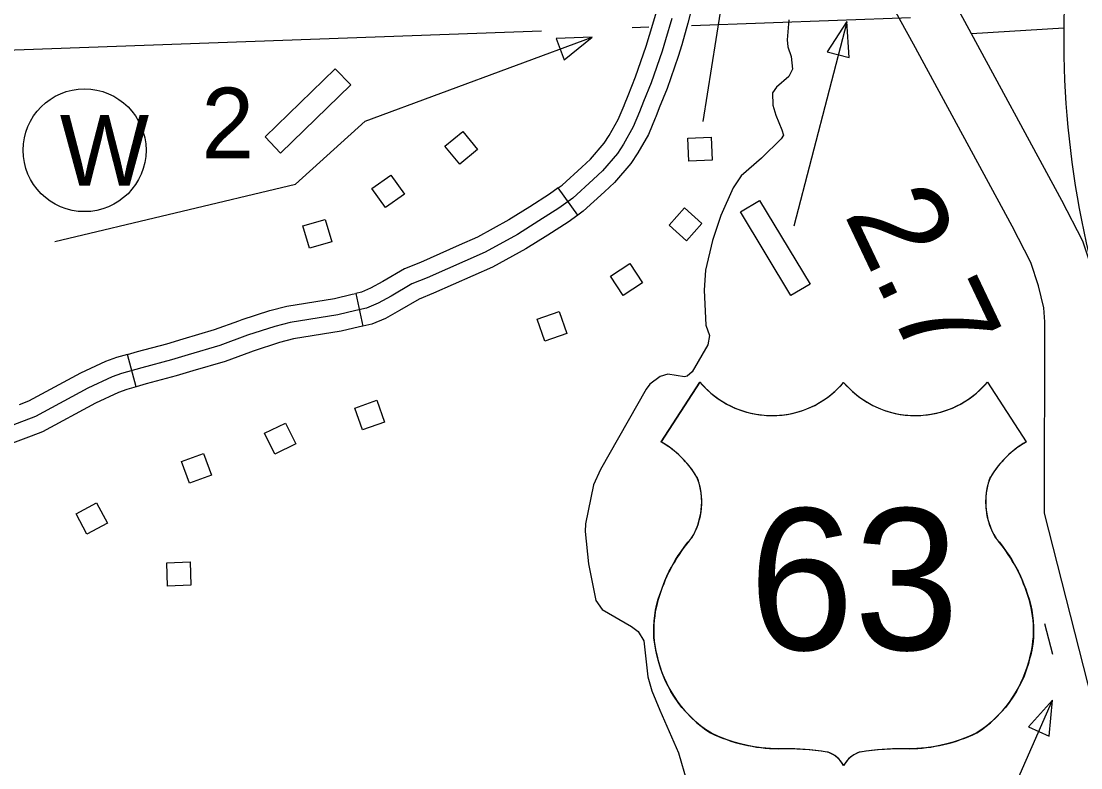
# Model space of a CAD drawing. Extents: x 1671357 to 13005564, y 567358 to 14261451.
# Drawn here: x 12758298.676 to 12758300.259, y 14259942.041 to 14259943.158 of the extents above; entities that cross this region are included whole.
import ezdxf

# ---------------------------------------------------------------- set-up
doc = ezdxf.new("R2010")
doc.units = 0
for name, color, linetype in [('15', 7, 'Continuous'), ('22', 7, 'Continuous'), ('31', 7, 'Continuous'), ('32', 7, 'Continuous'), ('35', 7, 'Continuous'), ('4', 7, 'Continuous'), ('48', 7, 'Continuous'), ('49', 7, 'Continuous'), ('56', 7, 'Continuous'), ('57', 7, 'Continuous'), ('63', 7, 'Continuous')]:
    doc.layers.add(name, color=color, linetype=linetype)

msp = doc.modelspace()

# ---------------------------------------------------------------- linework, layer by layer
at = {"layer": '15'}
for points in [[(12758299.593, 14259943.9275), (12758299.6236, 14259943.8747), (12758299.6719, 14259943.806), (12758299.8204, 14259943.6294), (12758299.8655, 14259943.5569), (12758300.0827, 14259943.1633), (12758300.2306, 14259942.8901), (12758300.2619, 14259942.8294), (12758300.2768, 14259942.7845), (12758300.2866, 14259942.742), (12758300.2893, 14259942.7116), (12758300.2887, 14259942.4326), (12758300.6474, 14259941.0247)], [(12758300.5675, 14259941.0004), (12758300.2052, 14259942.4222), (12758300.2058, 14259942.7081), (12758300.204, 14259942.7289), (12758300.1964, 14259942.7619), (12758300.1847, 14259942.7969), (12758300.1568, 14259942.8511), (12758300.0094, 14259943.1233), (12758299.7935, 14259943.5146), (12758299.7527, 14259943.5802), (12758299.6057, 14259943.7551), (12758299.5532, 14259943.8296), (12758299.5425, 14259943.8482), (12758299.5157, 14259943.9046)]]:
    msp.add_lwpolyline(points, dxfattribs=at)
at = {"layer": '22'}
for p, q in [((12758299.6902, 14259942.6181), (12758299.6324, 14259942.5287)), ((12758300.1199, 14259942.6181), (12758300.1776, 14259942.5287))]:
    msp.add_line(p, q, dxfattribs=at)
for centre, radius, start, end in [((12758299.7978, 14259942.7086), 0.1406, 220.075, 319.6701), ((12758300.0122, 14259942.7086), 0.1406, 220.3299, 319.925), ((12758299.5569, 14259942.399), 0.1501, 30.7809, 59.9883), ((12758300.2532, 14259942.399), 0.1501, 120.0117, 149.2191), ((12758299.59, 14259942.4386), 0.1029, 328.8105, 21.2108), ((12758300.2201, 14259942.4386), 0.1029, 158.7892, 211.1895), ((12758299.8591, 14259942.2276), 0.2401, 138.9565, 162.6913), ((12758299.951, 14259942.2276), 0.2401, 17.3087, 41.0435), ((12758299.7798, 14259942.2473), 0.1586, 160.9576, 197.3819), ((12758300.0302, 14259942.2473), 0.1586, 342.6181, 19.0424), ((12758299.8056, 14259942.2478), 0.1836, 195.1074, 237.1312), ((12758300.0044, 14259942.2478), 0.1836, 302.8688, 344.8926), ((12758299.8091, 14259942.3056), 0.2357, 244.0771, 269.5779), ((12758300.001, 14259942.3056), 0.2357, 270.4221, 295.9229), ((12758299.8145, 14259941.6381), 0.4318, 81.1942, 90.9539), ((12758299.8685, 14259942.0253), 0.0414, 28.0342, 72.9864), ((12758299.9416, 14259942.0253), 0.0414, 107.0136, 151.9658), ((12758299.9955, 14259941.6381), 0.4318, 89.0461, 98.8058)]:
    msp.add_arc(centre, radius, start, end, dxfattribs=at)
at = {"layer": '31'}
for p, q in [((12758299.5076, 14259942.8677), (12758299.4783, 14259942.9083)), ((12758299.1761, 14259942.7507), (12758299.1863, 14259942.7017)), ((12758299.0012, 14259942.7099), (12758299.0012, 14259942.7099)), ((12758298.8479, 14259942.6111), (12758298.8346, 14259942.6594))]:
    msp.add_line(p, q, dxfattribs=at)
for points in [[(12758299.5776, 14259943.0332), (12758299.5829, 14259943.0467), (12758299.5942, 14259943.0745), (12758299.6101, 14259943.1203), (12758299.6149, 14259943.1366), (12758299.6241, 14259943.1681), (12758299.629, 14259943.1875), (12758299.6309, 14259943.1966)], [(12758299.6799, 14259943.1864), (12758299.6778, 14259943.1762), (12758299.6724, 14259943.1549), (12758299.663, 14259943.1226), (12758299.6579, 14259943.105), (12758299.6411, 14259943.0569), (12758299.6294, 14259943.0281), (12758299.6242, 14259943.0149)], [(12758299.6483, 14259943.1615), (12758299.639, 14259943.1296), (12758299.634, 14259943.1127), (12758299.6176, 14259943.0657), (12758299.6061, 14259943.0374), (12758299.6001, 14259943.0221), (12758299.5907, 14259942.9995), (12758299.5761, 14259942.9738), (12758299.567, 14259942.96), (12758299.5448, 14259942.9339), (12758299.5306, 14259942.9209), (12758299.5001, 14259942.8931), (12758299.4793, 14259942.8781), (12758299.4494, 14259942.8591), (12758299.4176, 14259942.839), (12758299.3693, 14259942.8125), (12758299.2824, 14259942.7739), (12758299.2598, 14259942.7649), (12758299.2288, 14259942.7468), (12758299.2092, 14259942.7359), (12758299.1922, 14259942.7285), (12758299.176, 14259942.7251), (12758299.1492, 14259942.7186), (12758299.0779, 14259942.7072), (12758299.0548, 14259942.7012), (12758299.0142, 14259942.688), (12758298.9728, 14259942.6729), (12758298.9253, 14259942.6588), (12758298.9006, 14259942.6514), (12758298.8563, 14259942.6394), (12758298.826, 14259942.6311), (12758298.8118, 14259942.6258), (12758298.7758, 14259942.6092), (12758298.6972, 14259942.5666)], [(12758299.4783, 14259942.9083), (12758299.4843, 14259942.9126), (12758299.5137, 14259942.9394), (12758299.5267, 14259942.9513), (12758299.547, 14259942.9751), (12758299.5548, 14259942.9869), (12758299.5682, 14259943.0106), (12758299.5769, 14259943.0315), (12758299.5776, 14259943.0332)], [(12758299.6242, 14259943.0149), (12758299.6233, 14259943.0127), (12758299.6133, 14259942.9885), (12758299.5975, 14259942.9607), (12758299.5871, 14259942.9449), (12758299.5628, 14259942.9165), (12758299.5475, 14259942.9024), (12758299.5159, 14259942.8736), (12758299.5076, 14259942.8677)], [(12758299.4783, 14259942.9083), (12758299.4653, 14259942.8989), (12758299.436, 14259942.8803), (12758299.4048, 14259942.8606), (12758299.3581, 14259942.8349), (12758299.3306, 14259942.8227)], [(12758299.5076, 14259942.8677), (12758299.4934, 14259942.8574), (12758299.4628, 14259942.838), (12758299.4303, 14259942.8174), (12758299.3804, 14259942.79), (12758299.3509, 14259942.7769)], [(12758299.3306, 14259942.8227), (12758299.2727, 14259942.797), (12758299.2488, 14259942.7875), (12758299.2164, 14259942.7686), (12758299.1981, 14259942.7584), (12758299.1845, 14259942.7525), (12758299.1761, 14259942.7507)], [(12758299.3509, 14259942.7769), (12758299.2921, 14259942.7508), (12758299.2708, 14259942.7423), (12758299.2412, 14259942.725), (12758299.2203, 14259942.7134), (12758299.1998, 14259942.7045), (12758299.1863, 14259942.7017)], [(12758299.0012, 14259942.7099), (12758299.0061, 14259942.7117), (12758299.0477, 14259942.7252), (12758299.0727, 14259942.7317), (12758299.1442, 14259942.7432), (12758299.1705, 14259942.7495), (12758299.1761, 14259942.7507)], [(12758298.8346, 14259942.6594), (12758298.8498, 14259942.6636), (12758298.8937, 14259942.6754), (12758298.9182, 14259942.6828), (12758298.9649, 14259942.6967), (12758299.0012, 14259942.7099)], [(12758299.1863, 14259942.7017), (12758299.1815, 14259942.7007), (12758299.1541, 14259942.694), (12758299.083, 14259942.6826), (12758299.0618, 14259942.6771), (12758299.0224, 14259942.6644), (12758299.0184, 14259942.6629)], [(12758298.8346, 14259942.6594), (12758298.8183, 14259942.6549), (12758298.8022, 14259942.6489), (12758298.7646, 14259942.6316), (12758298.6867, 14259942.5894), (12758298.6731, 14259942.5842)], [(12758299.0184, 14259942.6629), (12758298.9807, 14259942.6491), (12758298.9325, 14259942.6348), (12758298.9075, 14259942.6273), (12758298.8629, 14259942.6153), (12758298.8479, 14259942.6111)], [(12758298.8479, 14259942.6111), (12758298.8337, 14259942.6072), (12758298.8215, 14259942.6027), (12758298.787, 14259942.5868), (12758298.7076, 14259942.5438), (12758298.6908, 14259942.5374)], [(12758298.6972, 14259942.5666), (12758298.6146, 14259942.5352), (12758298.572, 14259942.5309), (12758298.5393, 14259942.5213), (12758298.5057, 14259942.5012), (12758298.4691, 14259942.4706), (12758298.4448, 14259942.4415), (12758298.4283, 14259942.4191), (12758298.397, 14259942.3984), (12758298.3062, 14259942.3534), (12758298.2767, 14259942.3653)], [(12758298.6908, 14259942.5374), (12758298.6204, 14259942.5107), (12758298.5768, 14259942.5062), (12758298.5494, 14259942.4981), (12758298.5287, 14259942.4858)]]:
    msp.add_lwpolyline(points, dxfattribs=at)
at = {"layer": '32'}
msp.add_lwpolyline([(12758300.234, 14259943.1472), (12758300.0958, 14259943.139)], dxfattribs=at)
at = {"layer": '35'}
for points in [[(12758299.8233, 14259943.1596), (12758299.8206, 14259943.13), (12758299.8214, 14259943.1196), (12758299.8264, 14259943.1048), (12758299.8285, 14259943.0861), (12758299.8233, 14259943.0751), (12758299.8049, 14259943.0593), (12758299.7986, 14259943.0506), (12758299.7994, 14259943.0319), (12758299.8037, 14259943.017), (12758299.8126, 14259942.9953), (12758299.815, 14259942.9873), (12758299.8116, 14259942.9818), (12758299.7824, 14259942.9527), (12758299.7521, 14259942.9263), (12758299.7399, 14259942.9087), (12758299.7216, 14259942.867), (12758299.7092, 14259942.83), (12758299.6987, 14259942.7856), (12758299.6966, 14259942.7557), (12758299.6992, 14259942.7032), (12758299.7045, 14259942.6877), (12758299.7018, 14259942.6738), (12758299.6788, 14259942.6333), (12758299.6714, 14259942.6269), (12758299.6674, 14259942.6258), (12758299.6422, 14259942.6297), (12758299.6307, 14259942.6265), (12758299.6154, 14259942.6152), (12758299.6101, 14259942.6076)], [(12758299.6101, 14259942.6076), (12758299.5419, 14259942.4872), (12758299.5311, 14259942.4644), (12758299.5192, 14259942.4063), (12758299.5187, 14259942.3945), (12758299.5238, 14259942.3465), (12758299.5346, 14259942.2916), (12758299.5441, 14259942.2782), (12758299.5882, 14259942.2525), (12758299.5981, 14259942.2452), (12758299.6064, 14259942.2311), (12758299.6124, 14259942.1774), (12758299.6186, 14259942.1562), (12758299.6303, 14259942.1275), (12758299.6581, 14259942.0639), (12758299.6708, 14259942.0208), (12758299.6747, 14259941.9965), (12758299.6858, 14259941.9685), (12758299.6935, 14259941.8967), (12758299.7025, 14259941.8542), (12758299.7029, 14259941.7993), (12758299.7096, 14259941.7633), (12758299.7181, 14259941.7338)]]:
    msp.add_lwpolyline(points, dxfattribs=at)
at = {"layer": '4'}
for points in [[(12758300.0049, 14259943.1627), (12758299.6776, 14259943.1509)], [(12758299.4537, 14259943.1428), (12758298.5281, 14259943.1095), (12758298.5162, 14259943.1071), (12758297.6615, 14259943.0625)], [(12758299.6139, 14259943.1486), (12758299.5888, 14259943.1477)]]:
    msp.add_lwpolyline(points, dxfattribs=at)
at = {"layer": '49'}
for points in [[(12758299.6913, 14259942.1041), (12758299.6843, 14259942.11), (12758299.6776, 14259942.1163), (12758299.6696, 14259942.1245), (12758299.6634, 14259942.1317), (12758299.6579, 14259942.1388), (12758299.6523, 14259942.1468), (12758299.6469, 14259942.1556), (12758299.6427, 14259942.1632), (12758299.6389, 14259942.171), (12758299.6356, 14259942.1786), (12758299.6318, 14259942.1889), (12758299.6291, 14259942.1974), (12758299.6271, 14259942.2042), (12758299.6256, 14259942.2102), (12758299.6241, 14259942.2171), (12758299.6226, 14259942.2262), (12758299.6216, 14259942.2358), (12758299.6212, 14259942.244), (12758299.6212, 14259942.2523), (12758299.6218, 14259942.2612), (12758299.6227, 14259942.2693), (12758299.624, 14259942.2771), (12758299.6259, 14259942.2859), (12758299.628, 14259942.2935), (12758299.6303, 14259942.3004), (12758299.6331, 14259942.3087), (12758299.6356, 14259942.3155), (12758299.6378, 14259942.3208), (12758299.6409, 14259942.328), (12758299.6444, 14259942.3352), (12758299.6477, 14259942.3415), (12758299.6506, 14259942.3467), (12758299.6539, 14259942.3523), (12758299.6578, 14259942.3586), (12758299.6621, 14259942.3649), (12758299.6667, 14259942.3713), (12758299.6724, 14259942.3786), (12758299.677, 14259942.3842), (12758299.6809, 14259942.3903), (12758299.6846, 14259942.3982), (12758299.687, 14259942.4043), (12758299.6887, 14259942.4098), (12758299.6903, 14259942.4159), (12758299.6915, 14259942.4217), (12758299.6923, 14259942.4278), (12758299.6927, 14259942.4327), (12758299.6929, 14259942.4389), (12758299.6926, 14259942.4455), (12758299.6919, 14259942.4524), (12758299.6907, 14259942.4598), (12758299.689, 14259942.4667), (12758299.6867, 14259942.4736), (12758299.6838, 14259942.4793), (12758299.6806, 14259942.4841), (12758299.6773, 14259942.4887), (12758299.674, 14259942.4929), (12758299.6707, 14259942.4969), (12758299.6662, 14259942.502), (12758299.6617, 14259942.5065), (12758299.6573, 14259942.5106), (12758299.6523, 14259942.5149), (12758299.6461, 14259942.5197), (12758299.6415, 14259942.523), (12758299.6365, 14259942.5263), (12758299.6324, 14259942.5287), (12758299.6902, 14259942.6181), (12758299.6937, 14259942.6141), (12758299.6979, 14259942.6096), (12758299.7023, 14259942.6054), (12758299.7065, 14259942.6017), (12758299.7116, 14259942.5975), (12758299.7174, 14259942.5932), (12758299.7238, 14259942.589), (12758299.7295, 14259942.5857), (12758299.7357, 14259942.5824), (12758299.7425, 14259942.5793), (12758299.7499, 14259942.5764), (12758299.7587, 14259942.5735), (12758299.7659, 14259942.5717), (12758299.7737, 14259942.5701), (12758299.7799, 14259942.5691), (12758299.786, 14259942.5685), (12758299.7925, 14259942.5681), (12758299.7998, 14259942.568), (12758299.8089, 14259942.5684), (12758299.8156, 14259942.5691), (12758299.8228, 14259942.5702), (12758299.8296, 14259942.5716), (12758299.837, 14259942.5736), (12758299.8452, 14259942.5762), (12758299.8523, 14259942.579), (12758299.8617, 14259942.5833), (12758299.869, 14259942.5874), (12758299.8755, 14259942.5914), (12758299.8815, 14259942.5956), (12758299.8865, 14259942.5995), (12758299.8917, 14259942.6039), (12758299.8964, 14259942.6084), (12758299.9006, 14259942.6127), (12758299.905, 14259942.6176)], [(12758299.905, 14259942.6176), (12758299.9094, 14259942.6127), (12758299.9136, 14259942.6084), (12758299.9184, 14259942.6039), (12758299.9235, 14259942.5995), (12758299.9285, 14259942.5956), (12758299.9345, 14259942.5914), (12758299.941, 14259942.5874), (12758299.9484, 14259942.5833), (12758299.9577, 14259942.579), (12758299.9649, 14259942.5762), (12758299.973, 14259942.5736), (12758299.9804, 14259942.5716), (12758299.9873, 14259942.5702), (12758299.9945, 14259942.5691), (12758300.0011, 14259942.5684), (12758300.0102, 14259942.568), (12758300.0176, 14259942.5681), (12758300.024, 14259942.5685), (12758300.0301, 14259942.5691), (12758300.0363, 14259942.5701), (12758300.0441, 14259942.5717), (12758300.0513, 14259942.5735), (12758300.0601, 14259942.5764), (12758300.0676, 14259942.5793), (12758300.0743, 14259942.5824), (12758300.0805, 14259942.5857), (12758300.0862, 14259942.589), (12758300.0926, 14259942.5932), (12758300.0985, 14259942.5975), (12758300.1035, 14259942.6017), (12758300.1078, 14259942.6054), (12758300.1121, 14259942.6096), (12758300.1164, 14259942.6141), (12758300.1199, 14259942.6181), (12758300.1776, 14259942.5287), (12758300.1735, 14259942.5263), (12758300.1686, 14259942.523), (12758300.1639, 14259942.5197), (12758300.1577, 14259942.5149), (12758300.1528, 14259942.5106), (12758300.1484, 14259942.5065), (12758300.1439, 14259942.502), (12758300.1393, 14259942.4969), (12758300.136, 14259942.4929), (12758300.1328, 14259942.4887), (12758300.1295, 14259942.4841), (12758300.1263, 14259942.4793), (12758300.1233, 14259942.4736), (12758300.1211, 14259942.4667), (12758300.1194, 14259942.4598), (12758300.1181, 14259942.4524), (12758300.1174, 14259942.4455), (12758300.1172, 14259942.4389), (12758300.1174, 14259942.4327), (12758300.1178, 14259942.4278), (12758300.1186, 14259942.4217), (12758300.1197, 14259942.4159), (12758300.1213, 14259942.4098), (12758300.1231, 14259942.4043), (12758300.1254, 14259942.3982), (12758300.1292, 14259942.3903), (12758300.1331, 14259942.3842), (12758300.1377, 14259942.3786), (12758300.1434, 14259942.3713), (12758300.148, 14259942.3649), (12758300.1522, 14259942.3586), (12758300.1562, 14259942.3523), (12758300.1595, 14259942.3467), (12758300.1624, 14259942.3415), (12758300.1656, 14259942.3352), (12758300.1691, 14259942.328), (12758300.1723, 14259942.3208), (12758300.1744, 14259942.3155), (12758300.177, 14259942.3087), (12758300.1798, 14259942.3004), (12758300.182, 14259942.2935), (12758300.1841, 14259942.2859), (12758300.1861, 14259942.2771), (12758300.1874, 14259942.2693), (12758300.1883, 14259942.2612), (12758300.1888, 14259942.2523), (12758300.1889, 14259942.244), (12758300.1885, 14259942.2358), (12758300.1875, 14259942.2262), (12758300.186, 14259942.2171), (12758300.1845, 14259942.2102), (12758300.1829, 14259942.2042), (12758300.181, 14259942.1974), (12758300.1783, 14259942.1889), (12758300.1745, 14259942.1786), (12758300.1712, 14259942.171), (12758300.1674, 14259942.1632), (12758300.1632, 14259942.1556), (12758300.1578, 14259942.1468), (12758300.1521, 14259942.1388), (12758300.1467, 14259942.1317), (12758300.1405, 14259942.1245), (12758300.1325, 14259942.1163), (12758300.1257, 14259942.11), (12758300.1188, 14259942.1041)], [(12758299.905, 14259942.0447), (12758299.9025, 14259942.0489), (12758299.8997, 14259942.0525), (12758299.8962, 14259942.056), (12758299.8926, 14259942.0589), (12758299.89, 14259942.0606), (12758299.887, 14259942.0623), (12758299.8817, 14259942.0645), (12758299.8774, 14259942.0653), (12758299.8721, 14259942.0661), (12758299.8633, 14259942.0671), (12758299.8544, 14259942.0681), (12758299.8473, 14259942.0687), (12758299.8402, 14259942.0692), (12758299.8321, 14259942.0696), (12758299.8235, 14259942.0698), (12758299.8149, 14259942.0699), (12758299.806, 14259942.0699), (12758299.7957, 14259942.0702), (12758299.7822, 14259942.0714), (12758299.7714, 14259942.0729), (12758299.7615, 14259942.0747), (12758299.7508, 14259942.0772), (12758299.7414, 14259942.0798), (12758299.731, 14259942.0832), (12758299.7182, 14259942.0881), (12758299.7073, 14259942.093), (12758299.6986, 14259942.0986), (12758299.6913, 14259942.1041)], [(12758300.1188, 14259942.1041), (12758300.1115, 14259942.0986), (12758300.1028, 14259942.093), (12758300.0919, 14259942.0881), (12758300.0791, 14259942.0832), (12758300.0686, 14259942.0798), (12758300.0592, 14259942.0772), (12758300.0486, 14259942.0747), (12758300.0386, 14259942.0729), (12758300.0279, 14259942.0714), (12758300.0144, 14259942.0702), (12758300.0041, 14259942.0699), (12758299.9952, 14259942.0699), (12758299.9866, 14259942.0698), (12758299.978, 14259942.0696), (12758299.9698, 14259942.0692), (12758299.9627, 14259942.0687), (12758299.9557, 14259942.0681), (12758299.9467, 14259942.0671), (12758299.938, 14259942.0661), (12758299.9327, 14259942.0653), (12758299.9283, 14259942.0645), (12758299.9231, 14259942.0623), (12758299.9201, 14259942.0606), (12758299.9174, 14259942.0589), (12758299.9138, 14259942.056), (12758299.9104, 14259942.0525), (12758299.9076, 14259942.0489), (12758299.905, 14259942.0447)]]:
    msp.add_lwpolyline(points, dxfattribs=at)
at = {"layer": '56'}
for points in [[(12758299.695, 14259943.0076), (12758299.7275, 14259943.2125)], [(12758299.831, 14259942.8517), (12758299.9104, 14259943.1569)], [(12758299.1898, 14259943.0082), (12758299.5293, 14259943.1337)], [(12758298.7262, 14259942.8283), (12758299.0857, 14259942.914), (12758299.1898, 14259943.0082)], [(12758300.2053, 14259942.2569), (12758300.2171, 14259942.2111)], [(12758299.9958, 14259941.5365), (12758299.9637, 14259941.8626), (12758300.1169, 14259941.914), (12758300.2171, 14259942.1426)]]:
    msp.add_lwpolyline(points, dxfattribs=at)
for points in [[(12758299.8804, 14259943.1119), (12758299.9133, 14259943.1033), (12758299.9097, 14259943.1571)], [(12758299.4755, 14259943.132), (12758299.4873, 14259943.1), (12758299.5293, 14259943.1337)], [(12758299.1452, 14259943.0863), (12758299.1685, 14259943.0623), (12758299.0636, 14259942.9606), (12758299.0404, 14259942.9846)], [(12758299.3091, 14259942.9707), (12758299.3358, 14259942.9929), (12758299.3581, 14259942.9661), (12758299.3314, 14259942.9439)], [(12758299.6736, 14259942.9482), (12758299.6721, 14259942.9829), (12758299.7069, 14259942.9844), (12758299.7084, 14259942.9497)], [(12758299.2001, 14259942.9074), (12758299.2285, 14259942.9275), (12758299.2486, 14259942.8991), (12758299.2203, 14259942.879)], [(12758299.7509, 14259942.8726), (12758299.7795, 14259942.8898), (12758299.8548, 14259942.7646), (12758299.8262, 14259942.7474)], [(12758299.6442, 14259942.8528), (12758299.6674, 14259942.8786), (12758299.6933, 14259942.8553), (12758299.6701, 14259942.8295)], [(12758299.14, 14259942.828), (12758299.1067, 14259942.8181), (12758299.0968, 14259942.8516), (12758299.1302, 14259942.8614)], [(12758299.5753, 14259942.7475), (12758299.5565, 14259942.7767), (12758299.5857, 14259942.7956), (12758299.6046, 14259942.7664)], [(12758299.4471, 14259942.7123), (12758299.48, 14259942.7236), (12758299.4913, 14259942.6906), (12758299.4585, 14259942.6793)], [(12758299.1862, 14259942.5465), (12758299.1746, 14259942.5793), (12758299.2075, 14259942.5909), (12758299.2191, 14259942.5581)], [(12758299.0551, 14259942.5103), (12758299.0398, 14259942.5415), (12758299.0711, 14259942.5568), (12758299.0864, 14259942.5256)], [(12758298.9277, 14259942.4668), (12758298.9157, 14259942.4993), (12758298.9483, 14259942.5115), (12758298.9604, 14259942.4789)], [(12758298.7743, 14259942.3906), (12758298.7579, 14259942.4212), (12758298.7887, 14259942.4376), (12758298.805, 14259942.407)], [(12758298.8948, 14259942.313), (12758298.8935, 14259942.3477), (12758298.9283, 14259942.3491), (12758298.9296, 14259942.3143)], [(12758300.181, 14259942.1026), (12758300.2122, 14259942.0889), (12758300.2171, 14259942.1426)]]:
    msp.add_lwpolyline(points, close=True, dxfattribs=at)
at = {"layer": '57'}
msp.add_circle((12758298.7707, 14259942.9647), 0.0918, dxfattribs=at)
at = {"layer": '63'}
msp.add_arc((12758301.6325, 14259943.1312), 1.3986, 135.1742, 226.9585, dxfattribs=at)

# ---------------------------------------------------------------- texts
at = {"layer": '22'}
msp.add_text('63', height=0.21133, dxfattribs=at).set_placement((12758299.7633, 14259942.2177))
at = {"layer": '48'}
msp.add_text('2.7', height=0.14102, rotation=295.4068, dxfattribs=at).set_placement((12758299.905, 14259942.8694))
at = {"layer": '49'}
msp.add_text('63', height=0.21133, dxfattribs=at).set_placement((12758299.7633, 14259942.2177))
at = {"layer": '56'}
msp.add_text('2', height=0.1058, dxfattribs=at).set_placement((12758298.9453, 14259942.9525))
at = {"layer": '57'}
msp.add_text('W', height=0.1058, dxfattribs=at).set_placement((12758298.7336, 14259942.9118))

doc.saveas('drawing.dxf')
